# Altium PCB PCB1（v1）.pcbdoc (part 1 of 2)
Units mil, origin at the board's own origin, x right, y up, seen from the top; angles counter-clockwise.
Board outline 4301.67 x 3812.23 mil, 2 copper layers (Top Layer, Bottom Layer); 110 components, 92 nets, 368 pads, 77 vias.
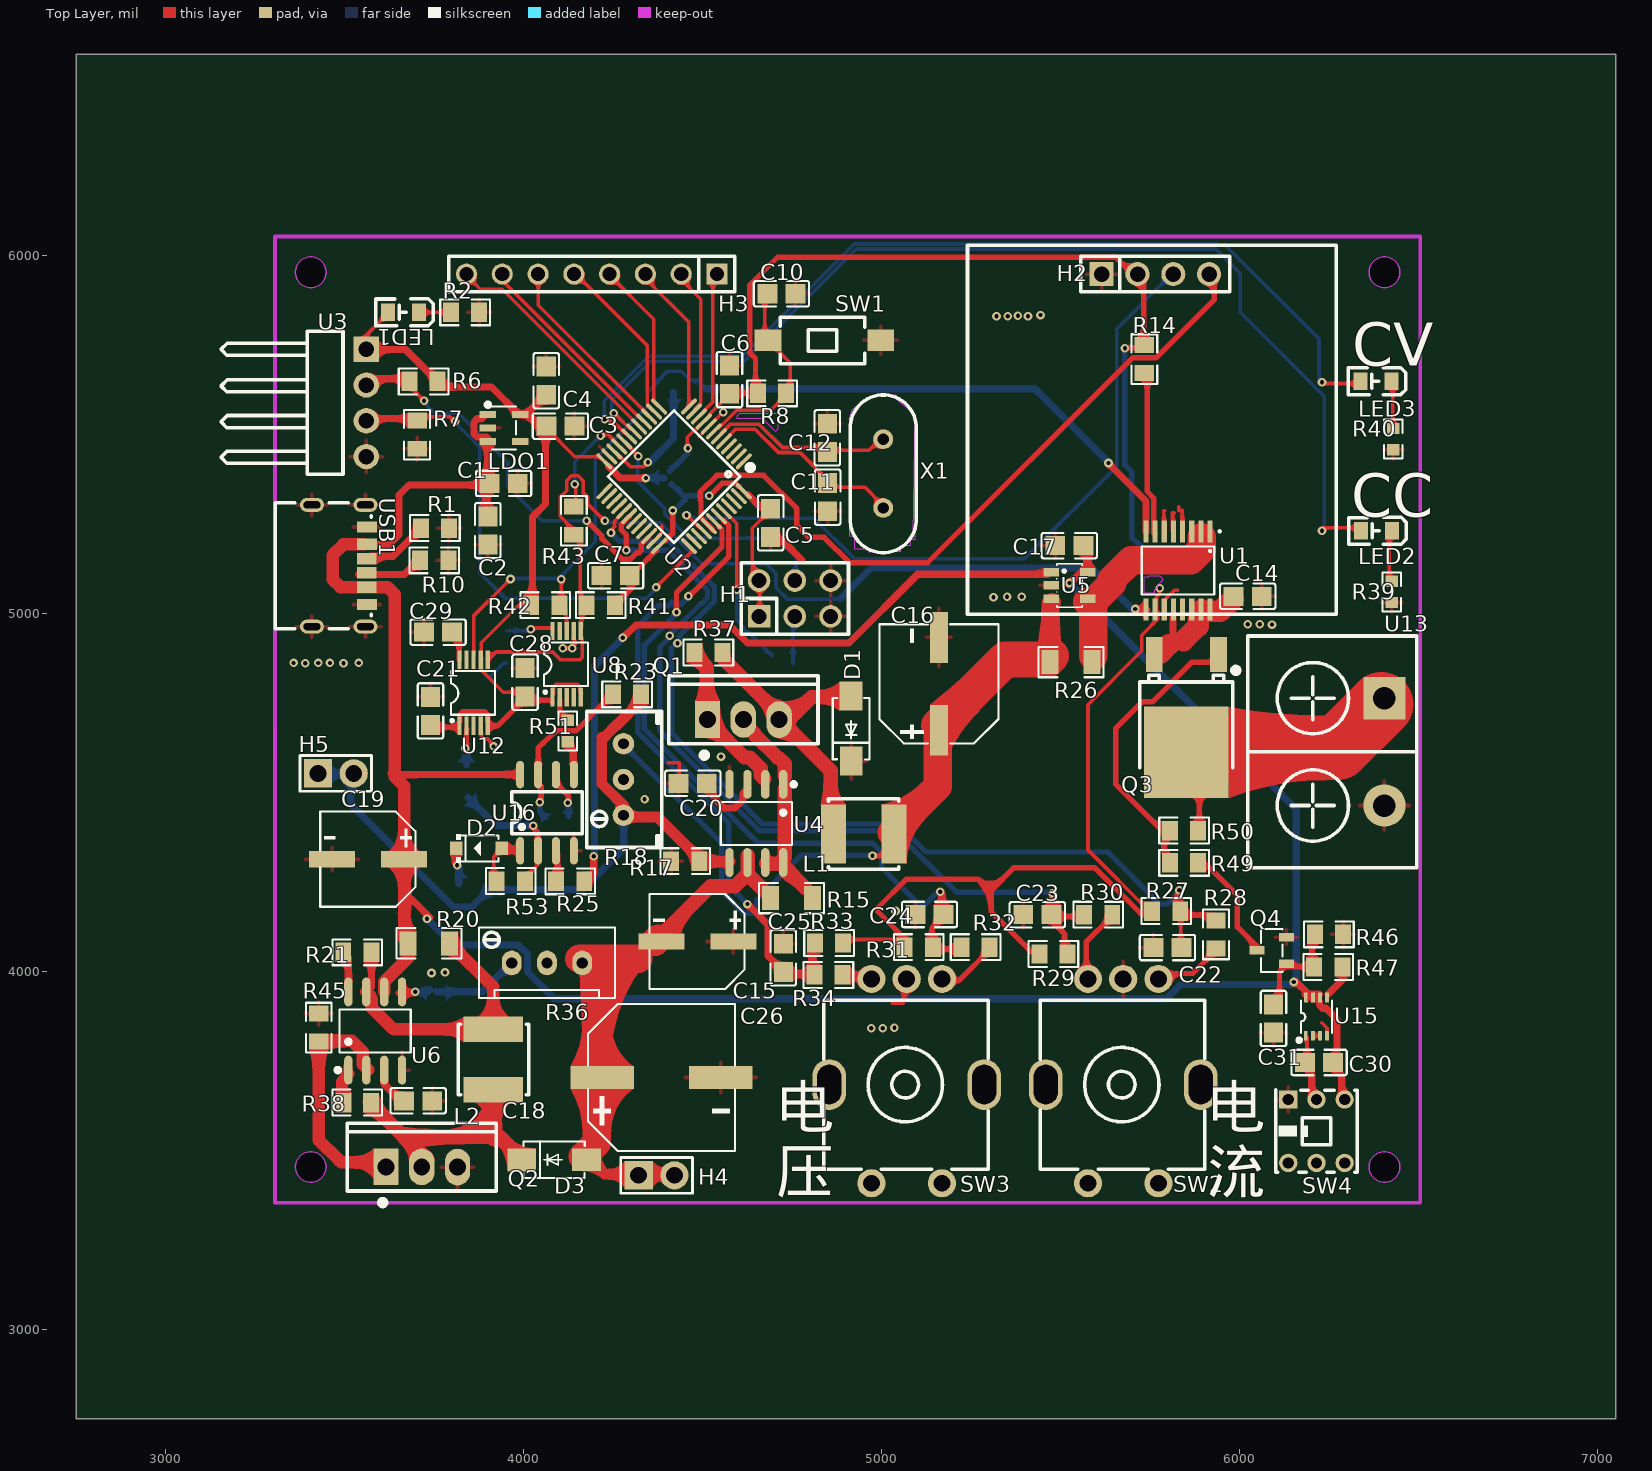
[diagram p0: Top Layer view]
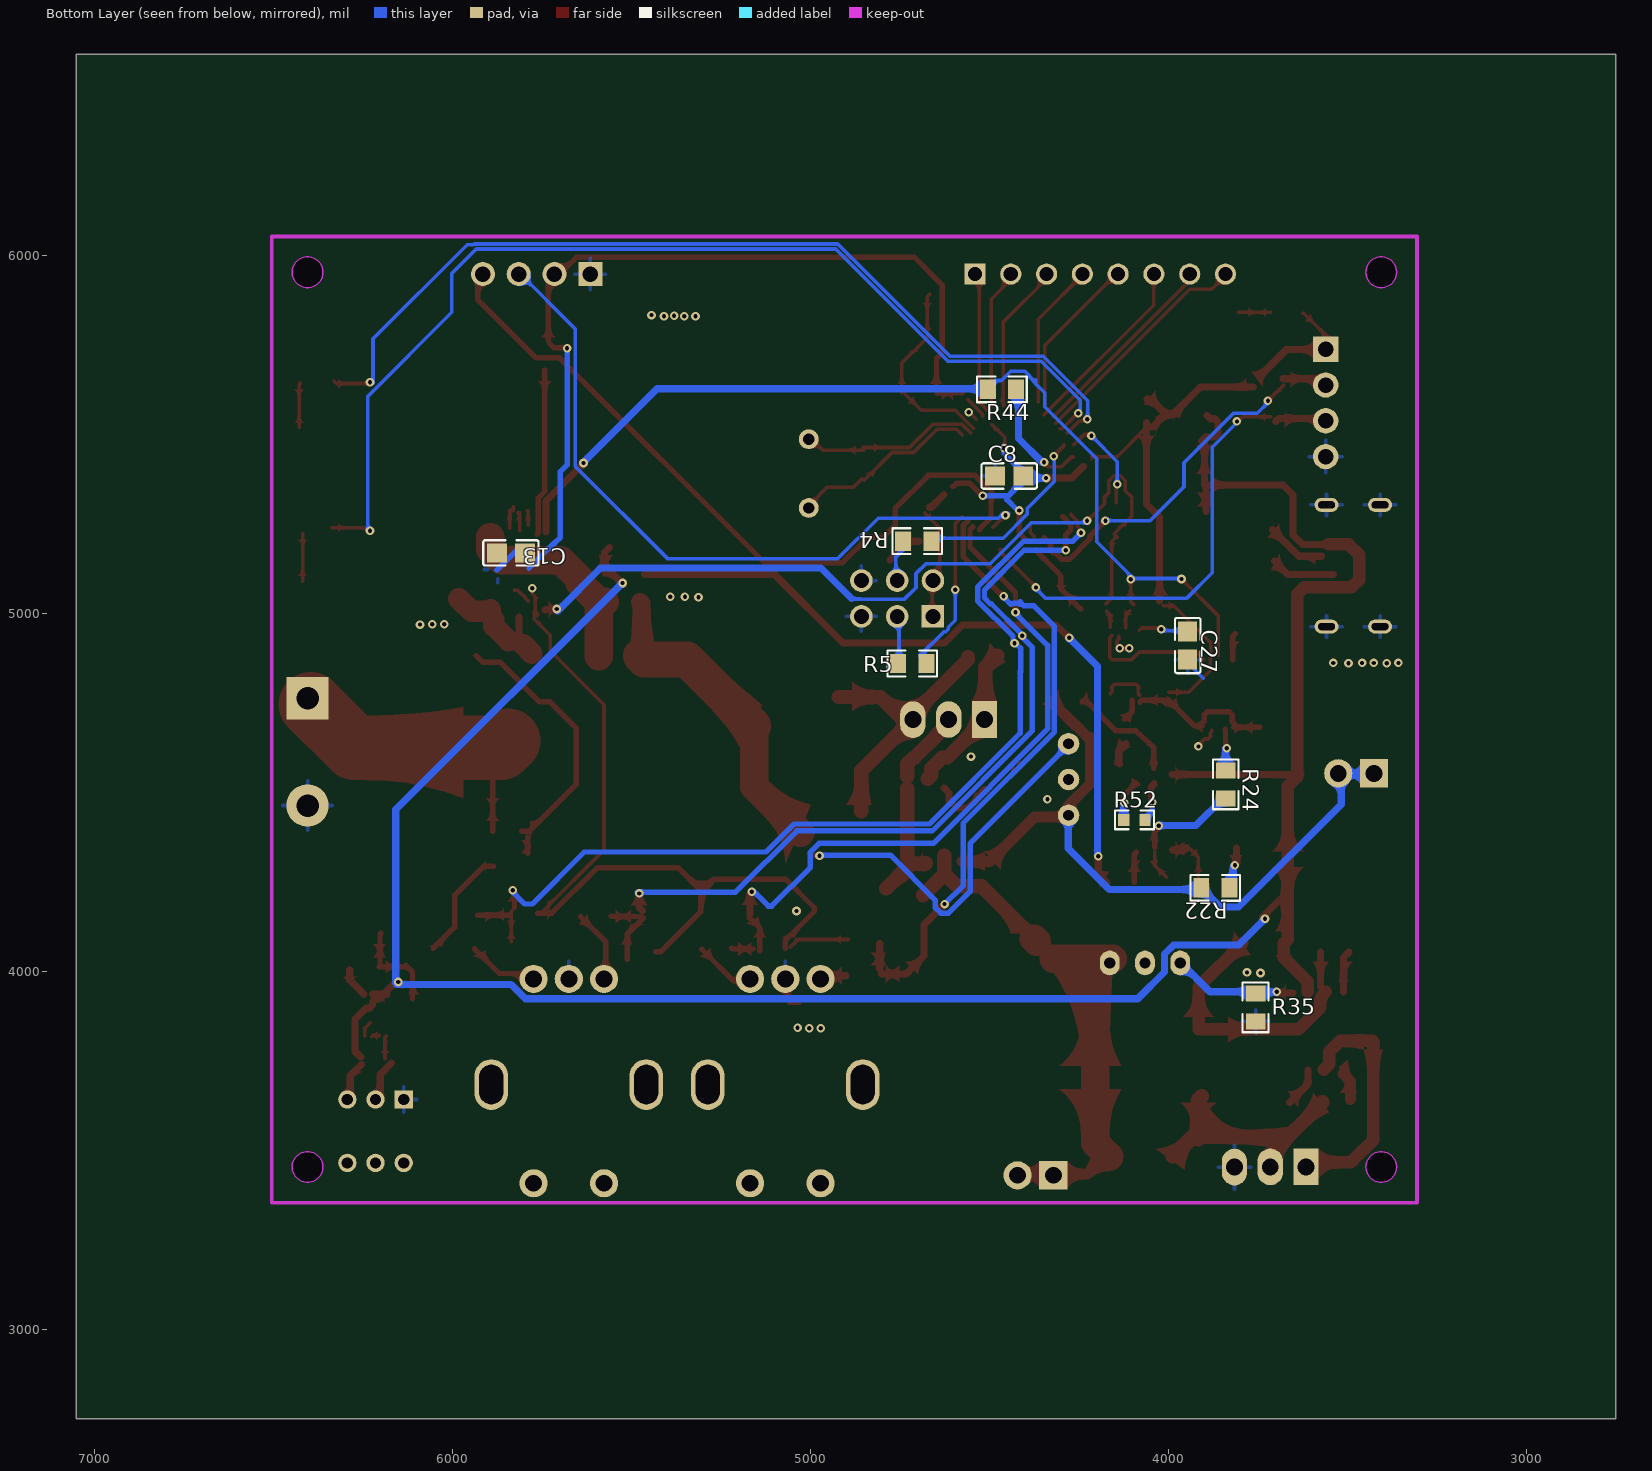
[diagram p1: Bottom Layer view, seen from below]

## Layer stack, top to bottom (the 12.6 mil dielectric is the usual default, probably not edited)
Top Layer: signal copper (thickness not stored)
Dielectric: dielectric 12.6, FR-4, Dk 4.8
Bottom Layer: signal copper (thickness not stored)

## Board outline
7051.67,2750 2750,2750 2750,6562.23 7051.67,6562.23
cut-out: 3448.37,3453.03 cw(c3405.37,3453.03) 3362.37,3453.03 cw(c3405.37,3453.03)
cut-out: 3448.37,5953.03 cw(c3405.37,5953.03) 3362.37,5953.03 cw(c3405.37,5953.03)
cut-out: 6448.38,5953.03 cw(c6405.37,5953.03) 6362.36,5953.03 cw(c6405.37,5953.03)
cut-out: 6448.37,3453.03 cw(c6405.37,3453.03) 6362.37,3453.03 cw(c6405.37,3453.03)

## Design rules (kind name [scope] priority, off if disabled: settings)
BoardOutlineClearance copperThickness1oz [All] p0: genericclearance=10 ignorepadtopadclearanceinfootprint=FALSE except(0: Arc-SplitContinuation Track-SplitContinuation SMDPad-SplitContinuation THPad-SplitContinuation Via-SplitContinuation Fill-SplitContinuation Poly-SplitContinuation Region-SplitContinuation Text-SplitContinuation; 6: Track-CutoutEdge SMDPad-CutoutEdge THPad-CutoutEdge Via-CutoutEdge Region-CutoutEdge; 11.8: Track-OutlineEdge SMDPad-OutlineEdge THPad-OutlineEdge Via-OutlineEdge Fill-OutlineEdge Region-OutlineEdge Poly-OutlineEdge Text-OutlineEdge Fill-CutoutEdge)
BoardOutlineClearance copperThickness2oz [All] p0: genericclearance=10 ignorepadtopadclearanceinfootprint=FALSE except(0: Arc-SplitContinuation Track-SplitContinuation SMDPad-SplitContinuation THPad-SplitContinuation Via-SplitContinuation Fill-SplitContinuation Poly-SplitContinuation Region-SplitContinuation Text-SplitContinuation; 6: Track-CutoutEdge SMDPad-CutoutEdge THPad-CutoutEdge Via-CutoutEdge Region-CutoutEdge; 11.8: Track-OutlineEdge SMDPad-OutlineEdge THPad-OutlineEdge Via-OutlineEdge Fill-OutlineEdge Region-OutlineEdge Poly-OutlineEdge Text-OutlineEdge Fill-CutoutEdge)
Clearance copperThickness1oz [(InNet('GND') OR InNet('+5V') OR InNet('VCC') OR InNet('PB11') OR InNet('RESET') OR InNet('OSCIN') OR InNet('OSCOUT') OR InNet('VIN') OR InNet('VOUT') OR InNet('$1N5169') OR InNet('$1N3483') OR InNet('$1N3468') OR InNet('PB13') OR InNet('PB12') OR InNet('PA10') OR InNet('PA11') OR InNet('PB14') OR InNet('PB15') OR InNet('PA8') OR InNet('PA9') OR InNet('PA12') OR InNet('PA15') OR InNet('PB3') OR InNet('PB4') OR InNet('PB5') OR InNet('PB6') OR InNet('PB7') OR InNet('PB8') OR InNet('PB9') OR InNet('VBAT') OR InNet('PC13') OR InNet('PC14') OR InNet('PC15') OR InNet('PA0') OR InNet('PA1') OR InNet('PA2') OR InNet('PA3') OR InNet('PA4') OR InNet('PA5') OR InNet('PA6') OR InNet('PA7') OR InNet('PB0') OR InNet('PB1') OR InNet('PB10') OR InNet('$1N3407') OR InNet('$1N3381') OR InNet('BOOT1') OR InNet('BOOT0') OR InNet('SWDIO') OR InNet('SWCLK') OR InNet('$1N3384') OR InNet('$1N3763') OR InNet('IN+') OR InNet('IN-') OR InNet('STEP-DOWN1') OR InNet('$1N26107') OR InNet('$1N14143') OR InNet('I-FB') OR InNet('$1N15305') OR InNet('$1N21810') OR InNet('$1N23905') OR InNet('$1N14411') OR InNet('$1N14439') OR InNet('$1N26304') OR InNet('$1N21463') OR InNet('$1N15295') OR InNet('$1N12640') OR InNet('DAC-VOUT') OR InNet('$1N14642') OR InNet('DAC-IOUT') OR InNet('$1N14584') OR InNet('I-VOUT') OR InNet('$1N19210') OR InNet('$1N19205') OR InNet('$1N19652') OR InNet('$1N19642') OR InNet('$1N21716') OR InNet('$1N26297') OR InNet('$1N36216') OR InNet('$1N36298') OR InNet('SDA2') OR InNet('SCL2') OR InNet('LODA+') OR InNet('$1N60568') OR InNet('$1N60719') OR InNet('$1N64537') OR InNet('$1N64545') OR InNet('PMOS-G') OR InNet('$1N64943') OR InNet('$1N65373') OR InNet('$1N65377') OR InNet('DAC-VOUT1'))] p1: gap=7 ignorepadtopadclearanceinfootprint=FALSE except(4: Track-Track; 6: Track-SMDPad SMDPad-SMDPad Track-THPad SMDPad-THPad THPad-THPad Track-Via SMDPad-Via THPad-Via Via-Via SMDPad-Fill THPad-Fill Via-Fill Fill-Fill Track-Region SMDPad-Region THPad-Region Via-Region Region-Region Track-Poly SMDPad-Poly THPad-Poly Via-Poly Fill-Poly Region-Poly Poly-Poly Track-Text SMDPad-Text THPad-Text Via-Text Fill-Text Region-Text Poly-Text Text-Text; 6.9: Track-Hole SMDPad-Hole THPad-Hole Via-Hole Fill-Hole Region-Hole Poly-Hole Text-Hole Sheet-Hole; 11.8: Track-Fill Fill-Region Track-Sheet SMDPad-Sheet THPad-Sheet Via-Sheet Fill-Sheet Region-Sheet Poly-Sheet Text-Sheet)
Clearance copperThickness2oz [All] p1: gap=7 ignorepadtopadclearanceinfootprint=FALSE except(6: Track-SMDPad SMDPad-SMDPad Track-THPad SMDPad-THPad THPad-THPad Track-Via SMDPad-Via THPad-Via Via-Via SMDPad-Fill THPad-Fill Via-Fill Fill-Fill Track-Region SMDPad-Region THPad-Region Via-Region Region-Region Track-Poly SMDPad-Poly THPad-Poly Via-Poly Fill-Poly Region-Poly Poly-Poly Track-Text SMDPad-Text THPad-Text Via-Text Fill-Text Region-Text Poly-Text Text-Text; 6.9: Track-Hole SMDPad-Hole THPad-Hole Via-Hole Fill-Hole Region-Hole Poly-Hole Text-Hole Sheet-Hole; 8: Track-Track; 11.8: Track-Fill Fill-Region Track-Sheet SMDPad-Sheet THPad-Sheet Via-Sheet Fill-Sheet Region-Sheet Poly-Sheet Text-Sheet)
DiffPairsRouting differentialPair [All] p1: maxuncoupledlength=10 minlimit=6 maxlimit=6 mostfreqgap=6 toplayer_minwidth=5 toplayer_prefwidth=10 toplayer_maxwidth=100 bottomlayer_minwidth=5 bottomlayer_prefwidth=10 bottomlayer_maxwidth=100
PasteMaskExpansion pasteMaskExpansion [All] p1: expansion=0
PlaneConnect innerPlane [All] p1: planeconnectstyle=Relief reliefexpansion=20 reliefentries=4 reliefconductorwidth=10 reliefairgap=10
PolygonConnect copperRegion [All] p1: connectstyle=Relief reliefentries=4 reliefconductorwidth=10 polygonreliefangle="90 Angle" airgapwidth=10
RoutingVias viaSize [All] p1: viastyle="Through Hole" holewidth=12.0078 minholewidth=11.811 maxholewidth=248.0314 width=24.0158 minwidth=19.685 maxwidth=393.7008
SolderMaskExpansion solderMaskExpansion [All] p1: useseparateexpansions=TRUE expansion=2 expansionbottom=2
Width copperThickness1oz [All] p1: maxlimit=200 minlimit=5 preferedwidth=10
Width copperThickness2oz [All] p1: maxlimit=100 minlimit=8 preferedwidth=30
Width +5V [All] p1: maxlimit=100 minlimit=20 preferedwidth=20

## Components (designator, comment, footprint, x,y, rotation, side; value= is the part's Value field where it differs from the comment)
C1 "0805B104K500NT" C0805 3944.11,5363.03 r180 top
C2 "CL21B105KBFNNNE" C0805 3900.03,5231.46 r90 top
C3 "CL21B105KBFNNNE" C0805 4102.83,5523.17 r180 top
C4 "0805B104K500NT" C0805 4063.27,5650.01 r270 top
C5 "0805B104K500NT" C0805 4690.37,5253.03 r90 top
C6 "0805B104K500NT" C0805 4575.37,5653.03 r270 top
C7 "0805B104K500NT" C0805 4257.17,5105.34 r0 top
C8 "0805B104K500NT" C0805 4444.75,5383.74 r180 bottom
C10 "0805B104K500NT" C0805 4720.37,5893.03 r0 top
C11 "0805CG220J500NT" C0805 4849.58,5324.66 r90 top
C12 "0805CG220J500NT" C0805 4848.74,5490.5 r270 top
C13 "0805B104K500NT" C0805 5837.1,5168.84 r180 bottom
C14 "0805B474K500NT" C0805 6023.31,5047.64 r180 top
C15 "MA35V100M6X8" CAP-SMD_BD6.3-L6.6-W6.6-RD 4485.37,4083.03 r0 top
C16 "MA25V470M8x10" CAP-SMD_BD8.0-L8.3-W8.3-LS9.0-FD_H10.5 5160.37,4803.03 r90 top
C17 "0805B104K500NT" C0805 5524.84,5189.32 r180 top
C18 "0805B152K500NT" C0805 3705.37,3638.03 r180 top
C19 "MA35V100M6X8" CAP-SMD_BD6.3-L6.6-W6.6-RD 3565.37,4313.03 r0 top
C20 "0805B471K500NT" C0805 4472.45,4524.86 r0 top
C21 "0805B104K500NT" C0805 3739.74,4727.4 r270 top
C22 "0805B103K500NT_C52278" C0805 5799.14,4066.12 r180 top
C23 "0805B103K500NT_C52278" C0805 5435.37,4158.03 r0 top
C24 "0805B103K500NT_C52278" C0805 5134.14,4158.64 r180 top
C25 "0805B103K500NT_C52278" C0805 4725.64,4037.51 r270 top
C26 "MA35V330M10x10" CAP-SMD_BD10.0-L10.3-W10.3-FD-LS11.0_H12.0 4385.37,3703.03 r0 top
C27 "0805B224K500NT" C0805 3946.03,4910.07 r90 bottom
C28 "0805B104K500NT" C0805 4004.05,4807.42 r270 top
C29 "0805B224K500NT" C0805 3761,4947.4 r0 top
C30 "0805B104K500NT" C0805 6222.71,3745.12 r180 top
C31 "0805B104K500NT" C0805 6095.37,3868.03 r90 top
D1 "SS34_C7420365" SMA_L4.3-W2.6-LS5.0-FD 4915.37,4678.03 r270 top
D2 "1N4148W_C7420318" SOD-123_L2.7-W1.6-LS3.7-FD 3875.37,4343.03 r180 top
D3 "SS34_C7420365" SMA_L4.3-W2.6-LS5.0-FD 4085.37,3473.03 r180 top
H1 "210-72-03GB01" HDR-TH_6P-P2.54-V-R2-C3-S2.54_A2541WV-2X3P 4757.86,5041.51 r0 top
H2 "2.54-1*4P母" HDR-TH_4P-P2.54-V-F 5765.37,5948.03 r0 top
H3 "PZ254V-11-08P" HDR-TH_8P-P2.54-V-M 4190.37,5948.03 r180 top
H4 "PZ254V-11-02P" HDR-TH_2P-P2.54-V-M 4371.51,3429.81 r0 top
H5 "PZ254V-11-02P" HDR-TH_2P-P2.54-V-M 3475.37,4553.03 r0 top
L1 "FNR5040S221MT" IND-SMD_L5.0-W5.0_FNR50XXS 4950.37,4383.03 r180 top
L2 "FNR5040S221MT" IND-SMD_L5.0-W5.0_FNR50XXS 3915.37,3753.03 r90 top
LDO1 "ME6211C33M5G-N" SOT-23-5_L3.0-W1.7-P0.95-LS2.8-BL 3945.37,5518.03 r270 top
LED1 "LS R976-NR-1-0-20-R18" LED0805-RD_RED 3664.63,5841.38 r180 top
LED2 "LS R976-NR-1-0-20-R18" LED0805-RD_RED 6383.02,5230.68 r180 top
LED3 "LS R976-NR-1-0-20-R18" LED0805-RD_RED 6382.05,5648.76 r180 top
Q1 "TIP31C_C963401" TO-220-3_L10.0-W4.5-P2.54-L 4613.92,4703.26 r0 top
Q2 "TIP31C_C963401" TO-220-3_L10.0-W4.5-P2.54-L 3715.37,3453.03 r0 top
Q3 "AOD4185_C400894" TO-252-3_L6.6-W6.1-P4.57-LS9.9-BR-CW 5852.14,4748.24 r90 top
Q4 "MMBT3904-E" SOT-23-3_L2.9-W1.4-P1.90-LS2.5-BR 6090.37,4058.03 r0 top
R1 "0805W8F5101T5E" R0805 3752.13,5238.33 r0 top
R2 "0805W8F1001T5E" R0805 3836.48,5841.03 r0 top
R4 "0805W8F1002T5E_C17414" R0805 4701.74,5201.8 r180 bottom
R5 "0805W8F1002T5E_C17414" R0805 4715.77,4859.77 r0 bottom
R6 "0805W8F1002T5E_C17414" R0805 3720.37,5648.03 r180 top
R7 "0805W8F1002T5E_C17414" R0805 3702.38,5499.31 r90 top
R8 "0805W8F1002T5E_C17414" R0805 4694.26,5614.86 r180 top
R10 "0805W8F5101T5E" R0805 3750.37,5148.03 r0 top
R14 "0805W8F4701T5E" R0805 5734.41,5710.49 r270 top
R15 "FRL1206FR220TS" R1206 4748.41,4204.45 r0 top
R17 "0805W8F1002T5E_C17414" R0805 4451.47,4307.65 r0 top
R18 "3296W-1-104LF" RES-ADJ-TH_3296W 4278.88,4535.69 r180 top
R20 "FRL1206FR220TS" R1206 3735.37,4078.03 r180 top
R21 "0805W8F1800T5E" R0805 3535.37,4053.03 r0 top
R22 "0805W8F1001T5E" R0805 3868.81,4233.19 r180 bottom
R23 "0805W8F1003T5E" R0805 4289.23,4773.67 r0 top
R24 "0805W8F1001T5E" R0805 3839.75,4521.99 r270 bottom
R25 "0805W8F1001T5E" R0805 4130.03,4251.4 r180 top
R26 "RE1206F1R050" R1206 5529.51,4863.9 r0 top
R27 "0805W8F1002T5E_C17414" R0805 5795.37,4168.03 r0 top
R28 "0805W8F1002T5E_C17414" R0805 5934.77,4103.01 r270 top
R29 "0805W8F1002T5E_C17414" R0805 5480.37,4048.03 r0 top
R30 "0805W8F1002T5E_C17414" R0805 5605.37,4158.03 r0 top
R31 "0805W8F1002T5E_C17414" R0805 5104.14,4067.38 r0 top
R32 "0805W8F1002T5E_C17414" R0805 5262.88,4067.38 r0 top
R33 "0805W8F1002T5E_C17414" R0805 4853.46,4078.83 r180 top
R34 "0805W8F1002T5E_C17414" R0805 4851.66,3989.68 r0 top
R35 "0805W8F1002T5E_C17414" R0805 3756.36,3899.03 r90 bottom
R36 "3296W-1-104_C48997936" RES-ADJ-TH_3296W-1-203 4065.37,4023.03 r180 top
R37 "0805W8F1000T5E" R0805 4516.27,4890.63 r180 top
R38 "0805W8F100JT5E" R0805_NEW 3535.37,3633.03 r0 top
R39 "0603WAF1001T5E" R0603 6425.96,5059.97 r270 top
R40 "0603WAF1001T5E" R0603 6430,5486.98 r270 top
R41 "0805W8F1002T5E_C17414" R0805 4215.37,5023.03 r180 top
R42 "0805W8F1002T5E_C17414" R0805 4060.37,5023.03 r0 top
R43 "0805W8F1000T5E" R0805 4140.49,5258.98 r90 top
R44 "0805W8F1000T5E" R0805 4465.13,5625.95 r180 bottom
R45 "0805W8F1800T5E" R0805 3427.6,3842.54 r90 top
R46 "0805W8F5100T5E" R0805 6250.37,4103.03 r180 top
R47 "0805W8F1001T5E" R0805 6248.23,4011.72 r180 top
R49 "0805W8F1001T5E" R0805 5845.37,4303.03 r180 top
R50 "0805W8F1002T5E_C17414" R0805 5845.37,4393.03 r0 top
R51 "0603WAF1001T5E" R0603 4123.29,4671.38 r270 top
R52 "0603WAF1001T5E" R0603 4095.05,4422.94 r180 bottom
R53 "0805W8F1001T5E" R0805 3964.06,4251.88 r180 top
SW1 "TS-1101-C-W" SW-SMD_L6.0-W3.3-LS8.0 4840.37,5763.03 r0 top
SW2 "EC11N1525404" SW-TH_EC11NXXXX 5675.37,3693.03 r180 top
SW3 "EC11N1525404" SW-TH_EC11NXXXX 5070.37,3693.03 r180 top
SW4 "5.8 WSPT" SW-TH_6P-L5.8-W5.8-P2.00-LS4.5-TL_K8-5851E-L1 6215.37,3553.03 r0 top
U1 "INA260AIPWR" TSSOP-16_L5.0-W4.4-P0.65-LS6.4-BL-1 5828.49,5119.65 r180 top
U2 "STM32F103C8T6" LQFP-48_L7.0-W7.0-P0.50-LS9.0-BL 4420.37,5383.03 r135 top
U3 "2541WR-04P" HDR-TH_4P-P2.54-H-M-W10.4-N 3560.37,5588.03 r270 top
U4 "MC34063ADR" SOIC-8_L4.9-W3.9-P1.27-LS6.0-BL 4650.37,4413.03 r180 top
U5 "INA180A3IDBVR" SOT-23-5_L3.0-W1.7-P0.95-LS2.8-BR 5525.37,5078.03 r180 top
U6 "MC34063ADR" SOIC-8_L4.9-W3.9-P1.27-LS6.0-BL 3585.37,3833.03 r0 top
U8 "DAC60501MDGSR" VSSOP-10_L3.0-W3.0-P0.50-LS4.9-BL 4120.37,4858.03 r0 top
U12 "DAC60501MDGSR" VSSOP-10_L3.0-W3.0-P0.50-LS4.9-BL 3860.37,4778.03 r0 top
U13 "KF7.62-2P" CONN-TH_KF7.62-2P 6405.37,4613.03 r270 top
U15 "SN74LVC1G74DCUR" SSOP-8_L2.0-W2.3-P0.50-LS3.1-BR 6215.37,3873.03 r270 top
U16 "LM358DR" SOIC-8_L5.0-W4.0-P1.27-LS6.0-BL 4065.37,4443.03 r0 top
USB1 "UKDBBTAAA" USB-C-SMD 3485.37,5133.03 r270 top
X1 "YG8MLBBE2X" CRYSTAL-TH_L11.1-W4.7-P4.88 5004.87,5390.53 r270 top

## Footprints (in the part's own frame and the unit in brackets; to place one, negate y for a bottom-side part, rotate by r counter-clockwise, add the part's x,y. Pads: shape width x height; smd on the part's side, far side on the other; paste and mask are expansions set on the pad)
C0805 [mm]
  rect 1.41x1.35 smd: 1(-1,0) 2(1,0)
  silkscreen extent -1.96,-0.9 1.96,0.9
CAP-SMD_BD6.3-L6.6-W6.6-RD [mm]
  rect 3.26x1.15 smd: 1(2.555,0) 2(-2.555,0)
  silkscreen extent -3.39,-3.38 3.36,3.38
CAP-SMD_BD8.0-L8.3-W8.3-LS9.0-FD_H10.5 [mm]
  rect 3.61x1.26 smd: 1(-3.295,0) 2(3.295,0)
  silkscreen extent -4.23,-4.23 4.23,4.23
CAP-SMD_BD10.0-L10.3-W10.3-FD-LS11.0_H12.0 [mm]
  rect 4.5x1.65 smd: 1(-4.2,0) 2(4.2,0)
  silkscreen extent -5.23,-5.23 5.23,5.23
CONN-TH_KF7.62-2P [mm]
  rect 3x3 hole 1.6: 1(-3.81,0)
  round 3 hole 1.6: 2(3.81,0)
  silkscreen extent -8.22,-9.7 8.22,2.3
CRYSTAL-TH_L11.1-W4.7-P4.88 [mm]
  round 1.4 hole 0.8: 1(-2.44,0) 2(2.44,0)
  silkscreen extent -5.58,-2.35 5.61,2.35
HDR-TH_2P-P2.54-V-M [mm]
  rect 2x2 hole 1.2: 1(-1.27,0)
  round 2 hole 1.2: 2(1.27,0)
  silkscreen extent -2.54,-1.27 2.54,1.27
HDR-TH_4P-P2.54-H-M-W10.4-N [mm]
  rect 1.8x1.8 hole 1.1: 1(-3.81,0)
  round 1.8 hole 1.1: 2(-1.27,0) 3(1.27,0) 4(3.81,0)
  silkscreen extent -5.09,-10.27 5.07,-1.65
HDR-TH_4P-P2.54-V-F [mm]
  rect 1.7x1.7 hole 1.1: 1(-3.81,0)
  round 1.7 hole 1.1: 2(-1.27,0) 3(1.27,0) 4(3.81,0)
  silkscreen extent -5.29,-1.27 5.29,1.27
HDR-TH_6P-P2.54-V-R2-C3-S2.54_A2541WV-2X3P [mm]
  rect 1.6x1.6 hole 1.05: 1(-2.54,-1.27)
  round 1.6 hole 1.05: 2(-2.54,1.27) 3(0,-1.27) 4(0,1.27) 5(2.54,-1.27) 6(2.54,1.27)
  silkscreen extent -3.81,-2.54 3.81,2.54
HDR-TH_8P-P2.54-V-M [mm]
  rect 1.5x1.5 hole 1: 1(-8.89,0)
  round 1.5 hole 1: 2(-6.35,0) 3(-3.81,0) 4(-1.27,0) 5(1.27,0) 6(3.81,0) 7(6.35,0) 8(8.89,0)
  silkscreen extent -10.16,-1.27 10.16,1.27
IND-SMD_L5.0-W5.0_FNR50XXS [mm]
  rect 1.8x4.2 smd: 1(-2.15,0) 2(2.15,0)
  silkscreen extent -2.5,-2.5 2.5,2.5
LED0805-RD_RED [mm]
  rect 1x1.25 smd: 1(-1.1,0) 2(1.1,0)
  silkscreen extent -2.1,-0.95 1.98,0.96
LQFP-48_L7.0-W7.0-P0.50-LS9.0-BL [mm]
  oval 0.27x1.5 smd: 1(-2.75,-4.25) 2(-2.25,-4.25) 3(-1.75,-4.25) 4(-1.25,-4.25) 5(-0.75,-4.25) 6(-0.25,-4.25) 7(0.25,-4.25) 8(0.75,-4.25) 9(1.25,-4.25) 10(1.75,-4.25) 11(2.25,-4.25) 12(2.75,-4.25) 25(2.75,4.25) 26(2.25,4.25) 27(1.75,4.25) 28(1.25,4.25) 29(0.75,4.25) 30(0.25,4.25) 31(-0.25,4.25) 32(-0.75,4.25) 33(-1.25,4.25) 34(-1.75,4.25) 35(-2.25,4.25) 36(-2.75,4.25)
  oval 1.5x0.27 smd: 13(4.25,-2.75) 14(4.25,-2.25) 15(4.25,-1.75) 16(4.25,-1.25) 17(4.25,-0.75) 18(4.25,-0.25) 19(4.25,0.25) 20(4.25,0.75) 21(4.25,1.25) 22(4.25,1.75) 23(4.25,2.25) 24(4.25,2.75) 37(-4.25,2.75) 38(-4.25,2.25) 39(-4.25,1.75) 40(-4.25,1.25) 41(-4.25,0.75) 42(-4.25,0.25) 43(-4.25,-0.25) 44(-4.25,-0.75) 45(-4.25,-1.25) 46(-4.25,-1.75) 47(-4.25,-2.25) 48(-4.25,-2.75)
  silkscreen extent -3.59,-4.46 3.3,3.34
R0603 [mil]
  rect 31.75x34.02 smd: 1(-29.66,0) 2(29.66,0)
  silkscreen extent -55,-26 55,26
R0805 [mm]
  rect 1.133x1.377 smd: 1(-1,0) 2(1,0)
  silkscreen extent -1.76,-0.92 1.76,0.92
R0805_NEW [mil]
  rect 44.59x54.21 smd: 1(-38.04,0) 2(38.04,0)
  silkscreen extent -69,-36 69,36
R1206 [mil]
  rect 47.54x66.97 smd: 1(-58.22,0) 2(58.22,0)
  silkscreen extent -91,-42 91,42
RES-ADJ-TH_3296W [mil]
  round 60 hole 30: 1(0,100.01) 2(0,0.01) 3(0,-99.99)
  silkscreen extent -108,-190 102,190
RES-ADJ-TH_3296W-1-203 [mm]
  oval 1.4x1.75 hole 0.8: 1(-2.5,0) 2(0,0) 3(2.5,0)
  silkscreen extent -4.83,-2.53 4.83,2.48
SMA_L4.3-W2.6-LS5.0-FD [mm]
  rect 2.046x1.62 smd: 1(-2.304,-0.009) 2(2.304,0.009)
  silkscreen extent -2.17,-1.32 2.19,1.29
SOD-123_L2.7-W1.6-LS3.7-FD [mm]
  rect 0.88x0.96 smd: 1(-1.61,0) 2(1.61,0)
  silkscreen extent -1.38,-1 1.6,1
SOIC-8_L4.9-W3.9-P1.27-LS6.0-BL [mm]
  oval 0.588x2.045 smd: 1(-1.905,-2.772) 2(-0.635,-2.772) 3(0.635,-2.772) 4(1.905,-2.772) 5(1.905,2.772) 6(0.635,2.772) 7(-0.635,2.772) 8(-1.905,2.772)
  silkscreen extent -2.8,-2.92 2.53,1.52
SOIC-8_L5.0-W4.0-P1.27-LS6.0-BL [mil]
  oval 22.38x76.78 smd: 1(-75,-106.5) 2(-25,-106.5) 3(25,-106.5) 4(75,-106.5) 5(75,106.5) 6(25,106.5) 7(-25,106.5) 8(-75,106.5)
  silkscreen extent -98,-59 98,59
SOT-23-3_L2.9-W1.4-P1.90-LS2.5-BR [mm]
  rect 1.07x0.6 smd: 1(1.035,-0.95) 2(1.035,0.95) 3(-1.035,0)
  silkscreen extent -0.76,-1.52 0.76,1.52
SOT-23-5_L3.0-W1.7-P0.95-LS2.8-BL [mm]
  rect 0.49x1.157 smd: 1(-0.95,-1.154) 2(0,-1.154) 3(0.95,-1.154)
  rect 0.49x1.175 smd: 4(0.95,1.154) 5(-0.95,1.154)
  silkscreen extent -1.8,-1.29 1.53,0.85
SOT-23-5_L3.0-W1.7-P0.95-LS2.8-BR [mm]
  rect 1.1x0.6 smd: 1(1.3,-0.95) 2(1.3,0) 3(1.3,0.95) 4(-1.3,0.95) 5(-1.3,-0.95)
  silkscreen extent -0.9,-1.55 0.9,1.55
SSOP-8_L2.0-W2.3-P0.50-LS3.1-BR [mm]
  rect 0.7x0.26 smd: 1(1.35,-0.75) 2(1.35,-0.25) 3(1.35,0.25) 4(1.35,0.75) 5(-1.35,0.75) 6(-1.35,0.25) 7(-1.35,-0.25) 8(-1.35,-0.75)
  silkscreen extent -1.15,-1.37 1.81,1.1
SW-SMD_L6.0-W3.3-LS8.0 [mm]
  rect 1.9x1.5 smd: 1(-4,0) 2(4,0)
  silkscreen extent -3.14,-1.67 2.86,1.63
SW-TH_6P-L5.8-W5.8-P2.00-LS4.5-TL_K8-5851E-L1 [mm]
  rect 1.3x1.3 hole 0.8: 1(-2,2.25)
  round 1.3 hole 0.8: 2(0,2.25) 3(2,2.25) 4(-2,-2.25) 5(0,-2.25) 6(2,-2.25)
  silkscreen extent -2.9,-2.9 2.9,2.92
SW-TH_EC11NXXXX [mm]
  round 2 hole 1.2: A(-2.5,-7.25) B(2.5,-7.25) C(0,-7.25) D(-2.5,7.25) E(2.5,7.25)
  oval 2.4x3.6 hole 1.7 slot 2.8 at 90 deg: EH(-5.5,0.25) EH(5.5,0.25)
  silkscreen extent -5.8,-5.75 5.9,6.25
TO-220-3_L10.0-W4.5-P2.54-L [mm]
  rect 1.8x2.6 hole 1.2: 1(-2.54,0.005)
  oval 1.8x2.6 hole 1.2: 2(0,0.005)
  oval 1.8x2.6 hole 1.2 copper offset 0,0: 3(2.54,-0.005)
  silkscreen extent -5.3,-2.73 5.3,3.09
TO-252-3_L6.6-W6.1-P4.57-LS9.9-BR-CW [mm]
  rect 2.5x1.2 smd: 1(3.475,-2.286) 3(3.475,2.286)
  rect 6.5x6 smd: 2(-3.475,0)
  silkscreen extent -4.57,-3.7 2.55,3.3
TSSOP-16_L5.0-W4.4-P0.65-LS6.4-BL-1 [mm]
  rect 0.364x1.56 smd: 1(-2.275,-2.78) 2(-1.625,-2.78) 3(-0.975,-2.78) 4(-0.325,-2.78) 5(0.325,-2.78) 6(0.975,-2.78) 7(1.625,-2.78) 8(2.275,-2.78) 9(2.275,2.78) 10(1.625,2.78) 11(0.975,2.78) 12(0.325,2.78) 13(-0.325,2.78) 14(-0.975,2.78) 15(-1.625,2.78) 16(-2.275,2.78)
  silkscreen extent -3.03,-2.85 2.58,1.7
USB-C-SMD [mm]
  oval 1x1.7 hole 0.5 slot 1.2 at 90 deg: 1(-4.32,1.849) 2(-4.32,-1.951) 3(4.32,-1.951) 4(4.32,1.849)
  rect 0.8x1.4 smd: A5(-0.5,1.947) A9(1.52,1.948) A12(2.75,1.949) B5(0.5,1.947) B9(-1.52,1.951) B12(-2.75,1.949)
  silkscreen extent -4.47,-4.55 4.47,2.25
VSSOP-10_L3.0-W3.0-P0.50-LS4.9-BL [mm]
  rect 0.3x1.3 smd: 1(-1,-2.35) 2(-0.5,-2.35) 3(0,-2.35) 4(0.5,-2.35) 5(1,-2.35) 6(1,2.35) 7(0.5,2.35) 8(0,2.35) 9(-0.5,2.35) 10(-1,2.35)
  silkscreen extent -1.62,-2.08 1.52,1.54

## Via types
v1: diameter 24.02, hole 12.01, Top Layer to Bottom Layer, 77 vias

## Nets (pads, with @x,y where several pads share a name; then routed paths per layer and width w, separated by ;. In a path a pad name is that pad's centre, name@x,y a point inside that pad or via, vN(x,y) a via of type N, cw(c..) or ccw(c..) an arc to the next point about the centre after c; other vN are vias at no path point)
$1N3381: R1.1 USB1.A5 | length 167.9
  Top Layer w20: USB1.A5@3572.02,5159.37 3634.98,5159.37 R1.1@3709.17,5233.57
$1N3384: R10.1 USB1.B5 | length 180.6
  Top Layer w20: USB1.B5@3538.3,5108.78 3666.45,5108.78 R10.1@3703.55,5145.88
$1N3407: LED1.1 R2.1 | length 91.1
  Top Layer w10: LED1.1@3713.5,5840.99 R2.1@3804.56,5840.99
$1N3468: H1.4 R4.1 | length 106.4
  Bottom Layer w10: R4.1@4730.57,5188.13 4761.3,5157.4 H1.4@4761.3,5094.45
$1N3483: H1.3 R5.2 | length 128.4
  Bottom Layer w10: H1.3@4749.35,4986.55 4752.72,4983.18 R5.2@4752.72,4859.52
$1N3763: R14.2 U1.7 | length 467.1
  Top Layer w15: R14.2@5742.63,5678.9 5742.63,5340.33 5760.47,5322.48 5760.47,5224.6 U1.7@5764.27,5220.8
$1N5169: D1.1 L1.2 Q1.3 R37.1 | length 750.6
  Top Layer w20: Q1.3@4716.21,4701.93 Q1.3@4728.3,4689.84
  Top Layer w40: R37.1@4559.9,4877.8 4559.9,4871.05 Q1.3@4702.67,4728.28 ; Q1.3@4725.15,4686.69 Q1.3@4728.3,4689.84 ; L1.2@4857.86,4447.3 4857.86,4560.28 Q1.3@4728.3,4689.84 ; D1.1@4920.76,4766.5 4804.97,4766.5 Q1.3@4728.3,4689.84
$1N12640: R21.1 U6.8 | length 116.8
  Top Layer w20: R21.1@3496,4053.03 3510.37,4038.66 U6.8@3510.37,3942.18
$1N14143: C20.2 U4.3 | length 172.5
  Top Layer w20: C20.2@4513.23,4507.37 4537.81,4482.8 4537.81,4477.94 4559.81,4455.94 4590.92,4455.94 4612.93,4477.94 4612.93,4498.4 U4.3@4626.4,4511.87
$1N14411: D2.1 R53.2 U16.1 | length 144.2
  Top Layer w10: R53.2@3916.79,4249.86 3916.79,4319.56 D2.1@3940.03,4342.79
  Top Layer w20: D2.1@3949.24,4345.05 3955.74,4338.55 U16.1@3988.22,4338.55
$1N14439: D2.2 R22.2 | length 102.7
  Top Layer w20: D2.2@3809.85,4344.05 3809.85,4300.71 v1(3814.09,4296.46)
  Bottom Layer w20: v1(3814.09,4296.46) 3818.84,4291.71 R22.2@3818.84,4245.12
$1N14584: R25.2 U16.3 | length 86.1
  Top Layer w15: U16.3@4089.91,4332.54 4095.15,4327.3 R25.2@4095.15,4248.6
$1N14642: R24.2 R53.1 U16.2 | length 365.8
  Top Layer w10: R53.1@4005.23,4262.6 4038.2,4295.58 U16.2@4038.2,4334.55
  Top Layer w15: v1@4021.65,4405.29 4038.51,4388.43 U16.2@4038.51,4346.84
  Bottom Layer w20: R24.2@3844.78,4485.61 3923.47,4406.92 v1@4026.9,4406.92
  other v1: 4027.15,4406.92
$1N15295: Q2.1 R45.1 U6.2 | length 667.1
  Top Layer w35: R45.1@3426.41,3799.85 3427.54,3798.72 3427.54,3528.42 3485.06,3470.89 3485.57,3470.89 3490.49,3465.97 Q2.1@3605.16,3465.97 ; R45.1@3428.35,3805.6 3519.91,3805.6 3551.16,3774.35 3551.16,3739.57 U6.2@3566.16,3724.57
$1N15305: C18.2 U6.3 | length 111.8
  Top Layer w20: U6.3@3610.37,3723.88 3610.37,3683.66 C18.2@3661,3633.03
$1N19205: R30.2 SW2.B | length 192.6
  Top Layer w15: SW2.B@5571.82,3988.8 5571.82,4081.73 R30.2@5642.27,4152.18
$1N19210: R28.2 SW2.A | length 198.2
  Top Layer w15: SW2.A@5768.55,3993.77 5869.73,3993.77 R28.2@5938.3,4062.34
$1N19642: R34.2 SW3.B | length 66.2
  Top Layer w20: R34.2@4900.88,3987.59 4958.59,3987.59 SW3.B@4964.58,3981.59
$1N19652: R32.2 SW3.A | length 158.2
  Top Layer w15: SW3.A@5181.81,3974.47 5217.03,3974.47 R32.2@5303.97,4061.41
$1N21463: L2.2 R20.1 R21.2 U6.7 | length 822.4
  Top Layer w20: U6.7@3560.37,3942.18 3574.74,3956.55 R21.2@3574.74,4053.03
  Top Layer w35: U6.7@3560.37,3942.18 3571.35,3931.19 3571.35,3926.02 3575.31,3922.06 3575.31,3898.98 3636.61,3837.67 L2.2@3915.37,3837.67 3915.37,3956.25 R20.1@3793.59,4078.03
$1N21716: R35.2 R36.3 U6.5 | length 328.8
  Top Layer w20: U6.5@3652.02,3939.59 3694.23,3939.59 v1(3697,3942.36)
  Bottom Layer w20: v1(3697,3942.36) 3731.4,3942.36 R35.2@3737.95,3948.91 ; R35.2@3757.5,3942.81 3884.16,3942.81 R36.3@3963.6,4022.25
$1N21810: C27.2 U8.10 | length 119.3
  Top Layer w10: v1@4028.76,4959.15 4074.85,4959.15 U8.10@4081.59,4952.41
  Bottom Layer w10: C27.2@3953.44,4951.28 4010.77,4951.28 v1@4015.27,4955.78
  other v1: 4019.76,4955.78
$1N23905: C29.2 U12.10 | length 75.5
  Top Layer w15: C29.2@3813.53,4942.6 3820.28,4935.86 U12.10@3820.28,4869.9
$1N26107: Q1.1 R37.2 U4.2 | length 414.8
  Top Layer w40: R37.2@4477.83,4882.29 4511.56,4848.57 Q1.1@4511.56,4702.43 ; Q1.1@4523.55,4684.69 4530.07,4684.69 4617.35,4597.41 4631.93,4597.41 4662.93,4566.42 4662.93,4547.31 U4.2@4672.44,4537.8
$1N26297: R38.1 U6.1 | length 80.9
  Top Layer w30: R38.1@3491.21,3641.38 3491.21,3691.59 U6.1@3512.95,3713.33
$1N26304: D3.2 L2.1 Q2.2 R38.2 | length 629.9
  Top Layer w40: R38.2@3569.15,3633.51 Q2.2@3707.43,3495.24 ; 3685.35,3537.17 3916.93,3537.17 ; L2.1@3907.18,3651.08 3916.93,3641.34 3916.93,3537.17 ; 3916.93,3529.67 3916.93,3537.17 ; 3933.41,3537.17 D3.2@3988.12,3482.46
$1N36216: LED2.1 R39.1 | length 133.7
  Top Layer w10: LED2.1@6418.23,5223.66 6418.98,5222.91 R39.1@6418.98,5090.26
$1N36298: LED3.1 R40.1 | length 125.1
  Top Layer w10: LED3.1@6425.56,5644.26 6428.94,5640.89 R40.1@6428.94,5520.6
$1N60568: C30.2 SW4.2 U15.1 | length 169.1
  Top Layer w10: U15.1@6185.46,3818.95 6188.96,3815.45 C30.2@6188.96,3754.99
  Top Layer w20: C30.2@6170.82,3743.22 6202.3,3711.74 SW4.2@6202.3,3652.54
$1N60719: U15.2 U15.3 | length 22.7
  Top Layer w10: U15.2@6204.44,3820.44 6222.93,3820.44 U15.3@6225.93,3817.45
$1N64537: R47.1 U15.5 | length 84.5
  Top Layer w20: U15.5@6247.66,3935.87 6287.63,3975.84 R47.1@6287.63,4003.82
$1N64545: C31.2 Q4.1 R46.2 R47.2 | length 274.2
  Top Layer w15: C31.2@6112.22,3922.52 6112.22,3997.84 Q4.1@6131.33,4016.95 ; Q4.1@6127.21,4012.46 R47.2@6205.16,4012.46 ; R46.2@6200.66,4106.14 6202.91,4103.89 R47.2@6202.91,4013.21
$1N64943: Q3.1 R49.2 R50.1 | length 772.8
  Top Layer w15: R49.2@5789.83,4329.03 R50.1@5789.83,4374.56 ; R50.1@5806.69,4391.42 5785.48,4391.42 5654.78,4522.12 5654.78,4679.21 5728.44,4752.87 5756.73,4752.87 5867.43,4863.57 5916.3,4863.57 Q3.1@5934.84,4882.12
$1N65373: R51.2 U16.5 | length 65.5
  Top Layer w20: R51.2@4118.29,4636.09 4138.6,4615.77 4138.6,4581.8 U16.5@4136.61,4579.8
$1N65377: R52.1 U16.6 | length 100.2
  Top Layer w15: U16.6@4090.31,4525.37 4125.62,4490.06 v1@4125.62,4474.74
  Bottom Layer w15: v1@4125.28,4467.08 4125.95,4466.41 R52.1@4125.95,4432.44
  other v1: 4123.29,4470.74
+5V: C1.2 C2.2 C17.1 C19.1 C30.1 LDO1.1 LDO1.3 R20.2 SW4.3 U5.5 U6.6 U15.6 U15.7 U15.8 U16.8 USB1.A9 USB1.B9 | length 7268.7
  Top Layer w20: USB1.B9@3553.66,5192.87 3624.48,5192.28 3651.46,5219.26 3651.46,5330.55 3679.74,5358.83 C1.2@3895.51,5358.83 ; 3630.37,4553.03 3640.37,4543.03 ; 3640.37,4559.41 3650.25,4549.53 U16.8@3990.37,4549.53 ; 3666.31,4200.05 3688.04,4200.05 v1@3738.25,4149.84 ; LDO1.1@3892.03,5553.14 3882.55,5543.66 3870.55,5543.66 3861.19,5534.3 3861.19,5501.76 3870.55,5492.4 3895.43,5492.4 LDO1.3@3906.64,5481.19 ; C2.2@3895.19,5284.32 3895.19,5358.51 C1.2@3895.51,5358.83 ; LDO1.3@3897.65,5482.31 3898.78,5481.19 C1.2@3898.78,5361.89 ; C1.2@3898.56,5361.89 C1.2@3895.51,5358.83 ; C1.2@3898.78,5358.65 C1.2@3898.78,5358.83 ; v1@5522.81,5080.33 5566.28,5123.8 U5.5@5567.03,5123.8 ; C17.1@5561.8,5184.13 5575.79,5170.14 U5.5@5575.79,5119.68 ; v1@6150.8,3970.64 6158.3,3970.64 6192.77,3936.17 ; U15.8@6183.7,3935.87 U15.6@6223.17,3935.87 ; U15.7@6205.53,3922.83 6215.92,3922.83 6223.8,3914.95 6223.8,3905.78 6233.16,3896.42 6242.33,3896.42 6273.21,3865.54 6273.21,3776.61 C30.1@6256.89,3760.28 ; C30.1@6254.76,3739.47 6286.24,3707.99 SW4.3@6286.24,3636.05
  Top Layer w35: USB1.B9@3553.65,5192.87 3496.58,5192.87 3466.58,5162.87 3466.58,5094.4 3487.79,5073.19 USB1.A9@3562.08,5073.19 3620.21,5073.19 3640.37,5053.03 3640.37,4559.41 3640.37,4543.03 3665.96,4517.44 C19.1@3665.96,4313.03 3665.96,4089.22 R20.2@3677.15,4078.03 3677.15,4037.22 3610.37,3970.44 U6.6@3610.37,3942.18
  Bottom Layer w20: v1@3732.26,4144.59 3803.39,4073.46 3984.98,4073.46 4010.49,4047.95 4010.49,3998.1 4085.48,3923.11 5796.72,3923.11 5836.47,3962.87 v1@6156.52,3962.87 ; v1@5526.16,5084.22 6158.78,4451.59 v1@6158.78,3967.49
  other v1: 6152.3,3969.9 3730.01,4146.84 5525.06,5084.83
BOOT0: R5.1 U2.44 | length 440.2
  Top Layer w10: U2.44@4576.64,5270.28 4595.62,5251.3 v1(4595.62,5066.18)
  Bottom Layer w10: v1(4595.62,5066.18) 4595.62,4980.65 4615.38,4960.89 4615.38,4955.46 4621.82,4949.03 4627.24,4949.03 R5.1@4694.27,4882
BOOT1: R4.2 U2.20 | length 525.2
  Top Layer w10: U2.20@4292.43,5470.79 4292.43,5467.46 v1@4317.75,5442.14
  Bottom Layer w10: v1@4318.84,5438.63 4318.84,5368.44 4393.86,5293.42 4393.86,5277.88 4461.55,5210.19 R4.2@4656.33,5210.19 ; v1@4319.32,5439.11 v1@4323.08,5439.11
  other v1: 4320.41,5439.26
DAC-IOUT: R24.1 U12.2 | length 108.1
  Top Layer w15: v1@3840.04,4617.26 3840.39,4617.62 3840.39,4675.14 U12.2@3840.97,4675.72
  Bottom Layer w20: v1@3838.04,4625.01 3840.29,4622.76 R24.1@3840.29,4576.67
  other v1: 3837.16,4622.88
DAC-VOUT: R51.1 U8.2 | length 63.1
  Top Layer w15: U8.2@4100.74,4757.72 4100.74,4725.75 R51.1@4122.73,4703.76
DAC-VOUT1: R23.1 R52.2 U16.7 | length 408
  Top Layer w15: U16.7@4039.35,4527.04 4049.01,4517.38 v1@4049.01,4475.08 ; U16.7@4041.29,4567.61 4041.29,4624.57 4054.28,4637.56 ; 4054.5,4637.33 4091.08,4671.68 4145.88,4671.68 4228.71,4754.5 R23.1@4240.61,4754.5
  Bottom Layer w15: v1@4045.34,4466.41 4045.34,4445.43 R52.2@4060.66,4430.11
  other v1: 4045.34,4472.08
GND: C1.1 C2.1 C3.1 C4.1 C5.1 C6.1 C7.1 C8.1 C10.2 C11.1 C12.1 C13.1 C14.1 C15.1 C16.2 C17.2 C18.1 C19.2 C20.1 C21.1 C22.2 C23.1 C24.2 C25.1 C26.2 C27.1 C28.1 C29.1 C31.1 D1.2 H1.5 H1.6 H2.1 LDO1.2 Q2.3 Q4.2 R1.2 R2.2 R7.1 R10.2 R17.1 R35.1 R39.2 R40.2 R45.2 R46.1 SW1.2 SW2.C SW3.C SW4.1 U1.4 U1.5 U1.6 U1.11 U2.8 U2.23 U2.35 U2.47 U3.4 U4.4 U5.2 U6.4 U8.4 U8.7 U12.4 U13.2 U15.4 U16.4 USB1.1 USB1.2 USB1.3 USB1.4 USB1.A12 USB1.B12 | length 871.9
  Top Layer w10: U12.4@3879.22,4672.73 3879.22,4669.08 3882.85,4665.45 3882.85,4655.37 3889.29,4648.93 3899.36,4648.93 v1@3920.18,4628.12 ; v1(4109.17,4902.46) 4133.51,4902.46 4143.84,4912.79 4143.84,4919.41 4142.84,4920.41 4142.84,4924.04 U8.7@4139.26,4927.62 ; U8.7@4137.26,4929.62 U8.7@4139.26,4927.62 ; U8.7@4138.92,4935.3 4138.92,4928.43 U8.7@4139.26,4927.62 ; U2.35@4374.31,5213.92 4386.45,5226.05 4386.45,5244.75 ; 4404.83,4582.26 4435.09,4582.26 4435.09,4551.63 ; U2.8@4536.44,5542.03 4555.25,5560.84 v1@4555.9,5560.84 ; 5029.58,3910.06 5060.58,3910.06 SW3.C@5060.58,3958.77 ; U1.11@5788.1,5033.91 5797.54,5043.35 5797.54,5045.46 5803.98,5051.9 5806.09,5051.9 5818.66,5064.46 5827.31,5064.46 ; U1.6@5788.98,5246.89 5788.98,5286.36 5791.98,5286.36 ; U1.5@5812.96,5231.4 5812.96,5280.37 5817.46,5280.37 ; 5830.45,5297.36 5830.45,5287.36 5840.44,5287.36 U1.4@5840.44,5238.4 ; 6230.03,3856.08 6245.44,3840.67 U15.4@6245.44,3819.58
  Top Layer w20: C5.1@4696.86,5201.34 4725.45,5201.34 4777.77,5149.02
  Bottom Layer w10: 3902.19,4818.91 3944.02,4860.74 C27.1@3952.38,4860.74
  Bottom Layer w15: 5796.21,5177.29 5820.2,5177.29 5876.41,5121.08
  other v1: 4971.25,3841 5003.72,3841 5036.2,3842.48 5039.1,4168.2 4338.03,4480.58 4551.55,4599.85 3916.12,4628.12 3357.22,4861.44 3390.26,4860.63 3426.53,4861.44 3458.77,4861.44 3496.65,4860.63 3539.37,4861.44 4135.92,4902.44 6023.36,4969.34 6056.57,4969.34 6091.26,4968.6 5312.98,5045.09 5350.87,5046.08 5392.2,5046.08 4558.01,5562.32 5321.44,5830.13 5352.99,5830.13 5409.45,5830.13 5381.22,5831.79 5444.33,5833.45
I-FB: H5.1 H5.2 R17.2 R18.1 R22.1 R23.2 U4.5 | length 1927.3
  Top Layer w30: 4218.4,4641.59 4218.4,4524.06 4278.88,4463.58 R18.1@4278.88,4435.68 ; 4218.52,4653.7 4226.52,4653.7 4227.89,4655.08 4227.89,4656.8 4257.76,4686.67 4259.48,4686.67 R23.2@4328.94,4756.13 ; R18.1@4284.41,4430.93 4374.35,4430.93 4498.76,4306.52 U4.5@4576.7,4306.52
  Bottom Layer w20: H5.1@3429.44,4553.52 3432.81,4550.15 H5.2@3503.63,4550.15 ; H5.2@3517.12,4553.52 3517.12,4465.83 3803.79,4179.17 3854.38,4179.17 R22.1@3901.59,4226.39 ; R22.1@3912.08,4228.38 4165.02,4228.38 4279.69,4343.05 4279.69,4435.79 R18.1@4276.32,4439.17
I-VOUT: R25.1 U5.1 | length 2028.4
  Top Layer w20: R25.1@4171.59,4248.24 4196.04,4272.69 v1(4196.04,4321.26) ; v1(4277.29,4931.43) 4313.68,4967.82 4575.11,4967.82 4625.7,4917.23 4908.99,4917.23 5101.22,5109.46 U5.1@5463.09,5109.46
  Bottom Layer w20: v1(4196.04,4321.26) 4198.16,4323.38 4198.16,4852.3 v1(4277.29,4931.43)
IN+: R26.2 U1.1 U1.2 U1.3 U5.4 | length 564.1
  Top Layer w80: U5.4@5575.03,5032.85 5591.52,5016.37 R26.2@5591.52,4880.72 ; U5.4@5593.82,5029.13 5593.82,5034.2 5644.19,5084.57 5644.19,5095.24 5697.6,5148.65 5863.74,5148.65 5894.44,5179.35 U1.2@5894.44,5212.37
IN-: C14.2 Q3.3 U1.12 U1.14 U1.15 U1.16 | length 259.8
  Top Layer w20: U1.12@5814.67,4988.94 5814.67,4942.98 5822.66,4934.98
  Top Layer w60: Q3.3@5778.88,4888.89 5802.8,4912.81 ; 5843.84,4923.99 5884.44,4964.59 5884.44,4981.83 ; U1.15@5894.67,5005.43 U1.15@5894.67,5010.3 ; 5908.04,5005.43 5947.01,5005.43 C14.2@5982.48,5040.9
LODA+: Q3.2 R50.2 U13.1 | length 754.5
  Top Layer w15: R50.2@5888.1,4390.67 Q3.2@5888.1,4535.06
  Top Layer w180: Q3.2@5844.65,4644.38 5864.88,4624.15 6274.64,4624.15 U13.1@6396.05,4745.56
OSCIN: C11.2 U2.5 X1.2 | length 518.8
  Top Layer w10: U2.5@4576.23,5497.14 4576.23,5498.34 4591.72,5513.83 4647.56,5513.83 4712,5449.4 4772.36,5449.4 C11.2@4849.4,5372.35 ; C11.2@4856.15,5375.73 4879.76,5352.12 4953.95,5352.12 5001.17,5304.9 X1.2@5001.17,5299.85
OSCOUT: C12.2 U2.6 X1.1 | length 511.1
  Top Layer w10: U2.6@4552.62,5503.88 4576.59,5527.85 4658.84,5527.85 4723.27,5463.41 C12.2@4852.78,5463.41 ; C12.2@4851.44,5456.22 4966.11,5456.22 X1.1@5008.26,5498.38
PA0: H3.1 U2.10 | length 392.1
  Top Layer w10: U2.10@4505.56,5567.24 4528.93,5590.61 4528.93,5937.37 H3.1@4537.59,5946.03
PA1: H3.2 U2.11 | length 406.6
  Top Layer w10: H3.2@4431.64,5941.54 4495.34,5877.83 4495.34,5669.92 4495.54,5669.72 4495.54,5588.27 4478.85,5571.58 U2.11@4478.85,5568.31
PA2: H3.3 U2.12 | length 418.2
  Top Layer w10: H3.3@4330.46,5944.91 4460.87,5814.51 U2.12@4460.87,5580.68
PA3: H3.4 U2.13 | length 412.6
  Top Layer w10: H3.4@4234.24,5950.99 4363.24,5821.99 U2.13@4363.24,5591.82
PA4: H3.5 U2.14 | length 460.5
  Top Layer w10: H3.5@4138.12,5956.05 4345.53,5748.64 4345.53,5602.11 4345.19,5601.77 4345.19,5588.27 4345.53,5587.93 U2.14@4345.53,5581.7
PA5: H3.6 U2.15 | length 538.6
  Top Layer w10: H3.6@4041.16,5965.89 4041.16,5861.34 U2.15@4348.06,5554.44
PA6: H3.7 U2.16 | length 575.5
  Top Layer w10: H3.7@3933.24,5964.2 3933.24,5937.22 U2.16@4321.08,5549.38
PA7: H3.8 U2.17 | length 659.3
  Top Layer w10: H3.8@3830.38,5954.08 3879.28,5905.18 3939.99,5905.18 U2.17@4314.33,5530.83
PA8: C22.1 R27.2 R28.1 U2.29 | length 2727.9
  Top Layer w10: v1@4241.17,5229.09 4254.08,5242 4254.08,5257.24 4271.48,5274.64 U2.29@4271.48,5277.06 ; R27.2@5829.37,4173.77 5836.11,4167.03 C22.1@5836.11,4082.72
  Top Layer w15: R27.2@5827.18,4178.2 5827.18,4223.17 v1@5830.92,4226.92 ; R27.2@5838.25,4157.9 5839.38,4156.77 R28.1@5929.31,4156.77
  Bottom Layer w15: v1(4244.12,5224.91) 4267.12,5201.91 4404.11,5201.91 4532.92,5073.11 4532.92,5034.85 4434.29,4936.23 v1@4434.29,4926.39 ; 4412.69,4837.24 4414.15,4838.7 ; v1@4426.18,4915.93 4412.69,4902.44 4412.69,4840.16 4414.15,4838.7 ; v1@5834.81,4224.22 5798.58,4187.99 5777.36,4187.99 5632.16,4333.19 5124.43,4333.19 5046.23,4411.4 4667.73,4411.4 4414.15,4664.98 4414.15,4838.7
  other v1: 5831.72,4226.33 4430.08,4916.61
